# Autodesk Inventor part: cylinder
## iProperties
Shininess: 64.0
Length Units: 11269
Angle Units: 11279
Time Units: 11290
Mass Units: 11283
Length Display Precision: 3
Angle Display Precision: 2
Compacted: True
Part Number: cylinder
Document SubType Name: Modeling
Created: 2003-01
Designer: Owner
Density: 0.0
Volumn: 0.0
Area: 0.0
PropertySet Name: Model Information
Control State: 0
Master: False
Checked Out: False
Author: Owner
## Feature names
1. Extrusion1
2. Extrusion2
